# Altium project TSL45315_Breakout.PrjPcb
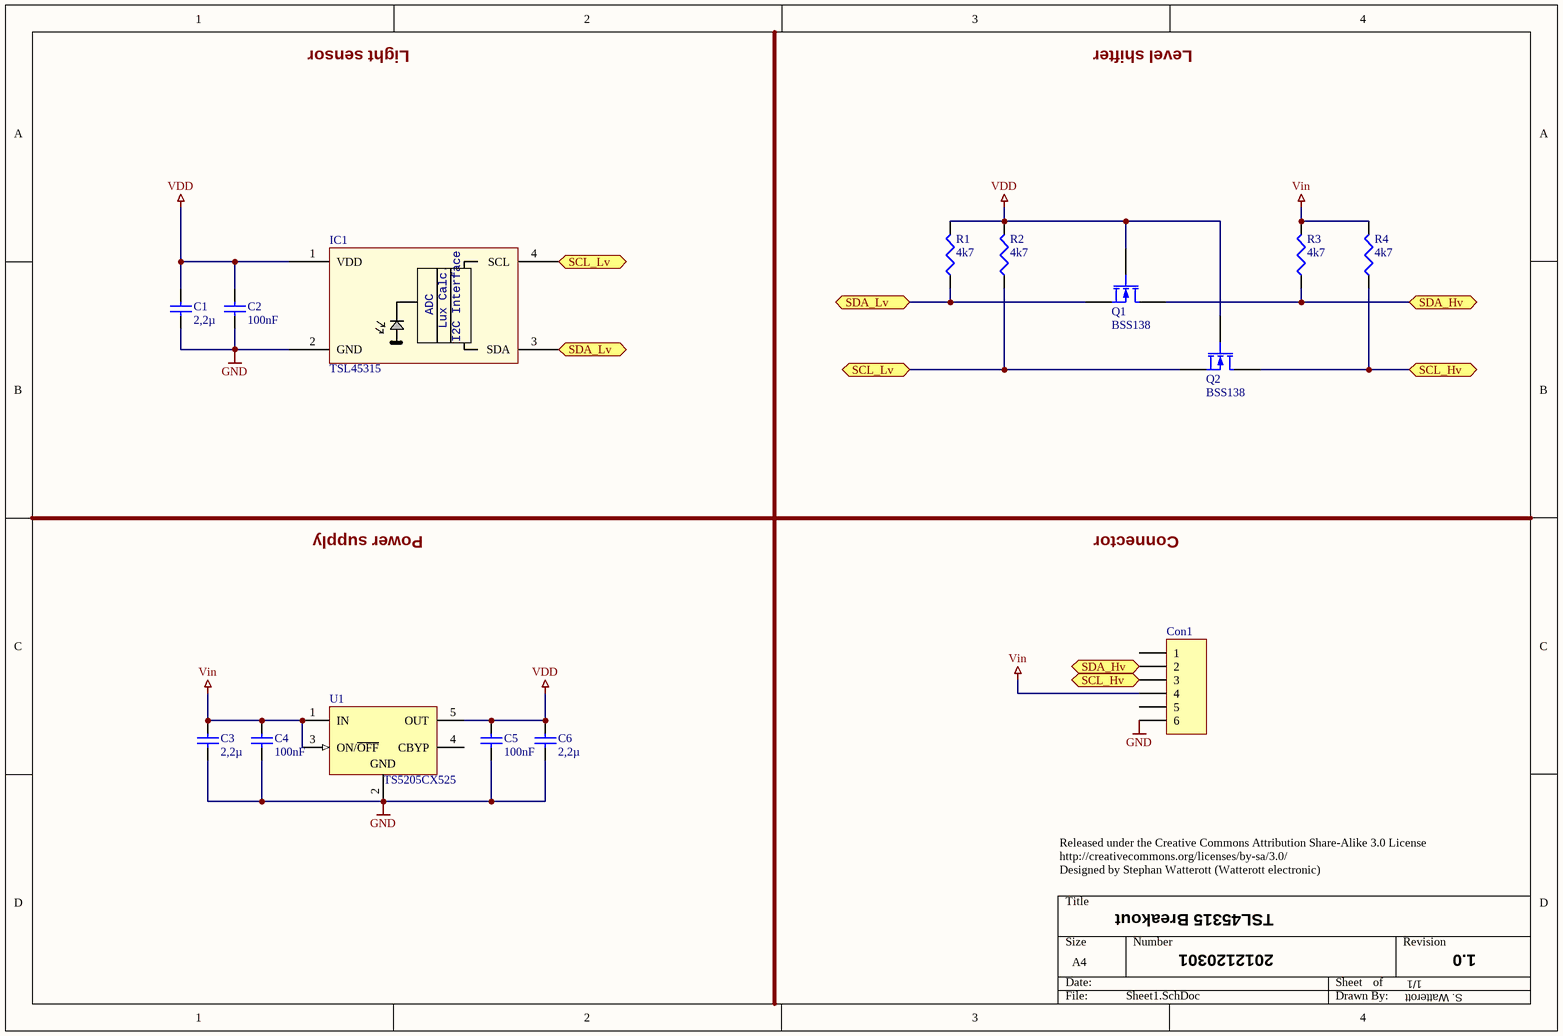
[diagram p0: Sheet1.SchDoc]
1 sheet, 15 parts. Net scope: flat (ports and power ports of the same name join across sheets).
Board file: PCB1.PcbDoc

## Sheet Sheet1.SchDoc
size A4

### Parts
C1  2,2µ  [0603]
C2  100nF  [0603]
C3  2,2µ  [0603]
C4  100nF  [0603]
C5  100nF  [0603]
C6  2,2µ  [0603]
Con1  Header 6H  [HDR1X6]  (value not drawn)
IC1  TSL45315  [TSL4531]
Q1  BSS138  [SOT23]
Q2  BSS138  [SOT23]
R1  4k7  [J1-0603]
R2  4k7  [J1-0603]
R3  4k7  [J1-0603]
R4  4k7  [J1-0603]
U1  TS5205CX525  [MF05A_N]

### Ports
SCL_Hv, SCL_Lv, SDA_Hv, SDA_Lv

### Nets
GND: C1.1 C2.1 C3.1 C4.1 C5.1 C6.1 Con1.6 IC1.2(GND) U1.2(GND)
VDD: C1.2 C2.2 C5.2 C6.2 IC1.1(VDD) Q1.3(G) Q2.3(G) R1.2 R2.2 U1.5(OUT)
Vin: C3.2 C4.2 Con1.4 R3.2 R4.2 U1.1(IN) U1.3(ON/~{OFF})
NetCon1_2: Con1.2 Q1.1(D) R3.1 ; port SDA_Hv
NetCon1_3: Con1.3 Q2.1(D) R4.1 ; port SCL_Hv
NetIC1_3: IC1.3(SDA) Q1.2(S) R1.1 ; port SDA_Lv
NetIC1_4: IC1.4(SCL) Q2.2(S) R2.1 ; port SCL_Lv

Not connected (* = marked no-connect by the designer): Con1 1 5; U1 4(CBYP)

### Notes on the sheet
- Light sensor
- Level shifter
- Power supply
- Connector
- Released under the Creative Commons Attribution Share-Alike 3.0 License
  http://creativecommons.org/licenses/by-sa/3.0/
  Designed by Stephan Watterott (Watterott electronic)
- TSL45315 Breakout
- 2012120301
- 1/1
- S. Watterott
- 1.0

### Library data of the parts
C1-C6 = C0603: Ceramic Chip Capacitor - Standard; Note: Footprint corresponds to dimensions for bulk cassette packaging. This case size has tightened tolerances.
Con1 = Header 6H: Header, 6-Pin, Right Angle
Q1 Q2 = BSS138: N-Channel Enhancement Mode Vertical DMOS FET
R1-R4 = Res3: Resistor
U1 = LP2985AIM5-2.5: Micropower 150 mA Low-Noise Ultra Low-Dropout Regulator in  SOT-23 and micro SMD Packages; Manufacturer: National Semiconductor; CompType: LDO IC; PackageTopMarking: LAUA*XTT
